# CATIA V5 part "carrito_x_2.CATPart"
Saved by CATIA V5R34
Part number: Part6.1
Bounding box of the stored display mesh (mm): x -30 to 30, y 0 to 70, z -5 to 10
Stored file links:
  C:\Users\Apolinar\Desktop\cnc\carrito_x_2.CATPart
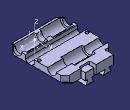
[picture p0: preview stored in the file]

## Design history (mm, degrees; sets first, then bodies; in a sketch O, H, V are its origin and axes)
AxisSystem1: origin (0, 0, 0), X (1, 0, 0), Y (0, 1, 0), Z (0, 0, 1)
Body1 (main body)
  Sketch1 on XY plane of AxisSystem1, origin (0, 0, 0), H (1, 0, 0), V (0, 1, 0)
    line L1 (-30, 70) -> (30, 70)
    line L2 (30, 70) -> (30, 0)
    line L3 (30, 0) -> (-30, 0)
    line L4 (-30, 0) -> (-30, 70)
    point P3 (30, 0)
    length L1 = 60
    length L2 = 70
    distance V L2 = 30
    horizontal: L1 H, L3 H
    vertical: L2 V, L4 V
    coincidence: P3 H
  Pad1: profile Sketch1, direction (0, 0, 1), length 10
  Sketch2 on end face of Pad1, origin (0, 0, 10), H (1, 0, 0), V (0, 1, 0)
    line L1 (-27, 18.35) -> (-3, 18.35)
    line L2 (-3, 18.35) -> (-3, 2.35)
    line L3 (-3, 2.35) -> (-27, 2.35)
    line L4 (-27, 2.35) -> (-27, 18.35)
    line L5 (3, 18.35) -> (27, 18.35)
    line L6 (27, 18.35) -> (27, 2.35)
    line L7 (27, 2.35) -> (3, 2.35)
    line L8 (3, 2.35) -> (3, 18.35)
    line L9 (-12, 58.35) -> (12, 58.35)
    line L10 (12, 58.35) -> (12, 42.35)
    line L11 (12, 42.35) -> (-12, 42.35)
    line L12 (-12, 42.35) -> (-12, 58.35)
    reference projected line E1 (-30, 70) -> (-30, 0) from edge [face of Pad1 from Sketch1.L4 | end face of Pad1]
    reference projected line E2 (30, 0) -> (30, 70) from edge [face of Pad1 from Sketch1.L2 | end face of Pad1]
    construction line L13 (-27, 10.35) -> (3, 10.35)
    point P13 (-27, 10.35)
    point P14 (3, 10.35)
    construction line L14 (-12, 50.35) -> (-4.1097, 50.35)
    point P15 (-12, 50.35)
    reference projected line E3 (-30, 0) -> (30, 0) from edge [face of Pad1 from Sketch1.L3 | end face of Pad1]
    axis line L15 (0, 52.893) -> (0, 58.35)
    point P17 (0, 58.35)
    length L9 = 24
    length L10 = 16
    length L4 = 16
    length L1 = 24
    length L5 = 24
    distance E1 L4 = 3
    distance L6 E2 = 3
    distance L13 L14 = 40
    distance L3 E3 = 2.35
    horizontal: L1 H, L3 H, L5 H, L7 H, L9 H, L11 H, L13 H, L14 H
    vertical: L2 V, L4 V, L6 V, L8 V, L10 V, L12 V, L15 V
    coincidence: L3 L7, P17 L9, L15 V
    midpoint: P15 L12, P13 L4, P14 L8, P17 L9
  Pocket1: profile Sketch2, direction (0, 0, -1), length 7.6
  Fillet1: radius 7.5, on edge [face of Pocket1 from Sketch2.L9 | end face of Pocket1]; edge [face of Pocket1 from Sketch2.L11 | end face of Pocket1]; edge [face of Pocket1 from Sketch2.L5 | end face of Pocket1]; edge [face of Pocket1 from Sketch2.L1 | end face of Pocket1]; edge [face of Pocket1 from Sketch2.L7 | end face of Pocket1]; edge [face of Pocket1 from Sketch2.L3 | end face of Pocket1]
  DatumCurve1
  DatumCurve2
  Sketch3 on face of Pad1 from Sketch1.L4, origin (-30, 0, 0), H (0, -1, 0), V (0, 0, 1)
    circle A1 centre (-49.85, 9.9) radius 5
    circle A2 centre (-9.85, 9.9) radius 5
    axis line L1 (-49.85, 9.9) -> (-9.85, 9.9)
    reference projected point E1 (-49.85, 9.9) from axis of face of Fillet1
    reference projected point E2 (-9.85, 9.9) from axis of face of Fillet1
    line L2 (-29.5, 3) -> (-19.5, 3)
    line L3 (-19.5, 3) -> (-19.5, 10)
    line L4 (-19.5, 10) -> (-29.5, 10)
    line L5 (-29.5, 10) -> (-29.5, 3)
    reference projected line E3 (-19.5, 15.2459) -> (-19.5, 23.2459) from edge of DatumCurve1
    reference projected line E4 (-29.5, 15.2459) -> (-29.5, 23.2459) from edge of DatumCurve2
    reference projected line E5 (-70, 0) -> (0, 0) from edge [start face of Pad1 | face of Pad1 from Sketch1.L4]
    reference projected line E6 (-70, 10) -> (0, 10) from edge [face of Pad1 from Sketch1.L4 | end face of Pad1]
    radius A1 = 5
    radius A2 = 5
    distance L2 E5 = 3
    concentricity: A1 E1, A2 E2
    horizontal: L2 H, L4 H
    vertical: L3 V, L5 V
    coincidence: E3 L3, E4 L5, L4 E6
  Pocket2: profile Sketch3, direction (1, 0, 0), through (limit type 3)
  Sketch4 on end face of Pad1, origin (0, 0, 10), H (1, 0, 0), V (0, 1, 0)
    circle A1 centre (-27.5, 32.851) radius 1.75
    point P1 (-27.5, 32.851)
    reference projected point E1 (-30, 44.851) from vertex [face of Pad1 from Sketch1.L4 | face of Pocket2 from Sketch3.A1 | end face of Pad1]
    circle A2 centre (27.5, 32.851) radius 1.75
    radius A1 = 1.75
    distance P1 V = 27.5
    distance E1 P1 V = 12
    symmetry: A1 A2 V
  Pocket3: profile Sketch4, direction (0, 0, -1), through (limit type 3)
  Plane1: type Angle, RefPlane ZX plane of AxisSystem1, Direction edge [ZX plane of AxisSystem1 | YZ plane of AxisSystem1], Angle 45
  DatumCurve3
  Sketch5 on start face of Pad1, origin (0, 0, 0), H (1, 0, 0), V (0, -1, 0)
    line L1 (11.5, -65) -> (30, -65)
    line L2 (30, -65) -> (30, -70)
    line L3 (30, -70) -> (11.5, -70)
    line L4 (11.5, -70) -> (11.5, -65)
    reference projected line E1 (30, -70) -> (-30, -70) from edge [start face of Pad1 | face of Pad1 from Sketch1.L1]
    line L5 (-0.8, -62.7) -> (1.5, -62.7)
    line L6 (1.5, -62.7) -> (1.5, -70)
    line L7 (1.5, -70) -> (-0.8, -70)
    line L8 (-0.8, -70) -> (-0.8, -62.7)
    reference projected line E2 (12.5, -66.0508) -> (12.5, -67.8268) from edge of DatumCurve3
    line L9 (-30, -60) -> (-20.8, -60)
    line L10 (-20.8, -60) -> (-20.8, -70)
    line L11 (-20.8, -70) -> (-30, -70)
    line L12 (-30, -70) -> (-30, -60)
    reference projected line E3 (-30, -70) -> (-30, 0) from edge [start face of Pad1 | face of Pad1 from Sketch1.L4]
    reference projected line E4 (30, 0) -> (30, -70) from edge [start face of Pad1 | face of Pad1 from Sketch1.L2]
    distance L1 E1 = 5
    length L6 = 7.3
    distance L6 E2 = 11
    length L5 = 2.3
    distance L10 L8 = 20
    length L12 = 10
    distance L6 L4 = 10
    horizontal: L1 H, L3 H, L5 H, L7 H, L9 H, L11 H
    vertical: L2 V, L4 V, L6 V, L8 V, L10 V, L12 V
    coincidence: L3 E1, L7 E1, L12 E3, L11 E1, L2 E4
  Pocket4: profile Sketch5, direction (0, 0, 1), through (limit type 6)
  Sketch6 on face of Pocket4 from Sketch5.L6, origin (1.5, 0, 0), H (0, -1, 0), V (0, 0, 1)
    circle A1 centre (-66.25, 4.55) radius 1.55
    reference projected line E1 (-70, 0) -> (-62.7, 0) from edge [start face of Pad1 | face of Pocket4 from Sketch5.L6]
    reference projected line E2 (-62.7, 0) -> (-62.7, 10) from edge [face of Pocket4 from Sketch5.L6 | face of Pocket4 from Sketch5.L5]
    radius A1 = 1.55
    distance A1 E1 = 3
    distance A1 E2 = 2
  Pad2: profile Sketch6, direction (-1, 0, 0), up to the existing solid (limit type 2)
  Sketch7 on face of Pad1 from Sketch1.L1, origin (0, 70, 0), H (-1, 0, 0), V (0, 0, 1)
    point P1 (-9, -1)
    line L1 (-9, -1) -> (-11, -5)
    point P2 (-11, -5)
    line L2 (-11, -5) -> (-2, -5)
    point P3 (-2, -5)
    line L3 (-2, -5) -> (-4, -1)
    point P4 (-4, -1)
    point P5 (-9, -1)
    line L4 (-9, -1) -> (-9, 0)
    point P6 (-9, 0)
    line L5 (-9, 0) -> (-4, 0)
    point P7 (-4, 0)
    line L6 (-4, 0) -> (-4, -1)
    reference projected line E1 (-30, 0) -> (30, 0) from edge [start face of Pad1 | face of Pad1 from Sketch1.L1]
    construction line L7 (-6.5, 0) -> (-6.5, -5)
    point P8 (-6.5, 0)
    point P9 (-6.5, -5)
    reference projected line E2 (-11.5, 0) -> (-11.5, 10) from edge [face of Pad1 from Sketch1.L1 | face of Pocket4 from Sketch5.L4]
    construction line L8 (-9, -1) -> (-4, -1)
    point P10 (-4, -1)
    axis line L9 (3.625, -5.1626) -> (3.625, -0.8078)
    point P13 (18.25, -5)
    point P14 (16.25, -1)
    line L10 (16.25, -1) -> (18.25, -5)
    point P15 (16.25, 0)
    point P16 (16.25, -1)
    line L11 (16.25, -1) -> (16.25, 0)
    point P17 (11.25, 0)
    line L12 (16.25, 0) -> (11.25, 0)
    point P18 (11.25, -1)
    line L13 (11.25, 0) -> (11.25, -1)
    point P19 (9.25, -5)
    line L14 (9.25, -5) -> (11.25, -1)
    line L15 (18.25, -5) -> (9.25, -5)
    length L2 = 9
    distance L7 E2 = 5
    length L5 = 5
    distance L2 P1 = 4
    length L4 = 1
    distance L6 L9 = 7.625
    horizontal: L2 H, L5 H, L8 H
    vertical: L4 V, L6 V, L7 V, L9 V
    coincidence: E1 L5, P1 P5, P10 L6, P10 P4
    midpoint: P8 L5, P9 L2
    symmetry: P2 P13 L9, P1 P14 L9, L1 L10 L9, P6 P15 L9, P5 P16 L9, L4 L11 L9, P7 P17 L9, L5 L12 L9, P4 P18 L9, L6 L13 L9, P3 P19 L9, L3 L14 L9, L2 L15 L9
  Pad3: profile Sketch7, direction (0, -1, 0), length 70
  DatumCurve4
  Sketch8 on face of Pocket4 from Sketch5.L6, origin (1.5, 0, 0), H (0, -1, 0), V (0, 0, 1)
    line L1 (-70, 10) -> (-62.7, 10)
    line L2 (-62.7, 10) -> (-62.7, 8)
    line L3 (-62.7, 8) -> (-70, 8)
    line L4 (-70, 8) -> (-70, 10)
    reference projected line E1 (-70, 10) -> (-62.7, 10) from edge of DatumCurve4
    reference projected line E2 (-62.7, 0) -> (-62.7, 10) from edge [face of Pocket4 from Sketch5.L6 | face of Pocket4 from Sketch5.L5]
    reference projected line E3 (-70, 0) -> (-70, 10) from edge [face of Pocket4 from Sketch5.L6 | face of Pad1 from Sketch1.L1]
    length L4 = 2
    horizontal: L1 H, L3 H
    vertical: L2 V, L4 V
    coincidence: L1 E1, L2 E2, E3 L4
  Pocket5: profile Sketch8, direction (1, 0, 0), length 10
  Sketch9 on start face of Pad1, origin (0, 0, 0), H (1, 0, 0), V (0, -1, 0)
    point P2 (-24.8, -32.851)
    construction circle A1 centre (-27.5, -32.851) radius 3.1177
    construction circle A2 centre (-27.5, -32.851) radius 2.7
    point P3 (-24.8, -34.4098)
    point P4 (-24.8, -31.2922)
    point P5 (-27.5, -29.7333)
    point P6 (-30.2, -31.2922)
    point P7 (-30.2, -34.4098)
    point P8 (-27.5, -35.9687)
    line L1 (-24.8, -34.4098) -> (-24.8, -31.2922)
    line L2 (-24.8, -31.2922) -> (-27.5, -29.7333)
    line L3 (-27.5, -29.7333) -> (-30.2, -31.2922)
    line L4 (-30.2, -31.2922) -> (-30.2, -34.4098)
    line L5 (-30.2, -34.4098) -> (-27.5, -35.9687)
    line L6 (-27.5, -35.9687) -> (-24.8, -34.4098)
    construction line L7 (-27.5, -32.851) -> (-24.8, -32.851)
    reference projected circle E1 centre (-27.5, -32.851) radius 1.75 from edge [face of Pocket3 from Sketch4.A1 | start face of Pad1]
    point P10 (24.8, -32.851)
    construction circle A3 centre (27.5, -32.851) radius 3.1177
    construction circle A4 centre (27.5, -32.851) radius 2.7
    point P11 (24.8, -34.4098)
    point P12 (24.8, -31.2922)
    point P13 (27.5, -29.7333)
    point P14 (30.2, -31.2922)
    point P15 (30.2, -34.4098)
    point P16 (27.5, -35.9687)
    construction line L8 (27.5, -32.851) -> (24.8, -32.851)
    line L9 (24.8, -34.4098) -> (24.8, -31.2922)
    line L10 (24.8, -31.2922) -> (27.5, -29.7333)
    line L11 (27.5, -29.7333) -> (30.2, -31.2922)
    line L12 (30.2, -31.2922) -> (30.2, -34.4098)
    line L13 (30.2, -34.4098) -> (27.5, -35.9687)
    line L14 (27.5, -35.9687) -> (24.8, -34.4098)
    distance L3 L6 = 5.4
    coincidence: A1 P3, A1 P4, A1 P5, A1 P6, A1 P7, A1 P8
    tangency: A2 L1, A2 L2, A2 L3, A2 L4, A2 L5, A2 L6
    midpoint: P2 L1
    horizontal: L7 H
    concentricity: A2 E1
    symmetry: P2 P10 V, A1 A3 V, A2 A4 V, P3 P11 V, P4 P12 V, P5 P13 V, P6 P14 V, P7 P15 V, P8 P16 V, L7 L8 V, L1 L9 V, L2 L10 V, L3 L11 V, L4 L12 V, L5 L13 V, L6 L14 V
  Pocket6: profile Sketch9, direction (0, 0, 1), length 3
  Chamfer1: length 5, angle 45, on edge [face of Pad3 | face of Pad1 from Sketch1.L4]; edge [face of Pad1 from Sketch1.L2 | face of Pad3]; edge [face of Pad1 from Sketch1.L4 | face of Pocket4 from Sketch5.L9]; edge [face of Pocket4 from Sketch5.L1 | face of Pad1 from Sketch1.L2]
  Fillet2: radius 3, on edge [face of Pocket2 from Sketch3.L3 | face of Pocket2 from Sketch3.L2]; edge [face of Pocket2 from Sketch3.L2 | face of Pocket2 from Sketch3.L5]
  Chamfer2: length 3, angle 45, on edge [start face of Pad1 | face of Chamfer1] (x4); edge [start face of Pad1 | face of Pad1 from Sketch1.L2] (x2); edge [start face of Pad1 | face of Pad3] (x3); edge [start face of Pad1 | face of Pad1 from Sketch1.L4] (x2)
